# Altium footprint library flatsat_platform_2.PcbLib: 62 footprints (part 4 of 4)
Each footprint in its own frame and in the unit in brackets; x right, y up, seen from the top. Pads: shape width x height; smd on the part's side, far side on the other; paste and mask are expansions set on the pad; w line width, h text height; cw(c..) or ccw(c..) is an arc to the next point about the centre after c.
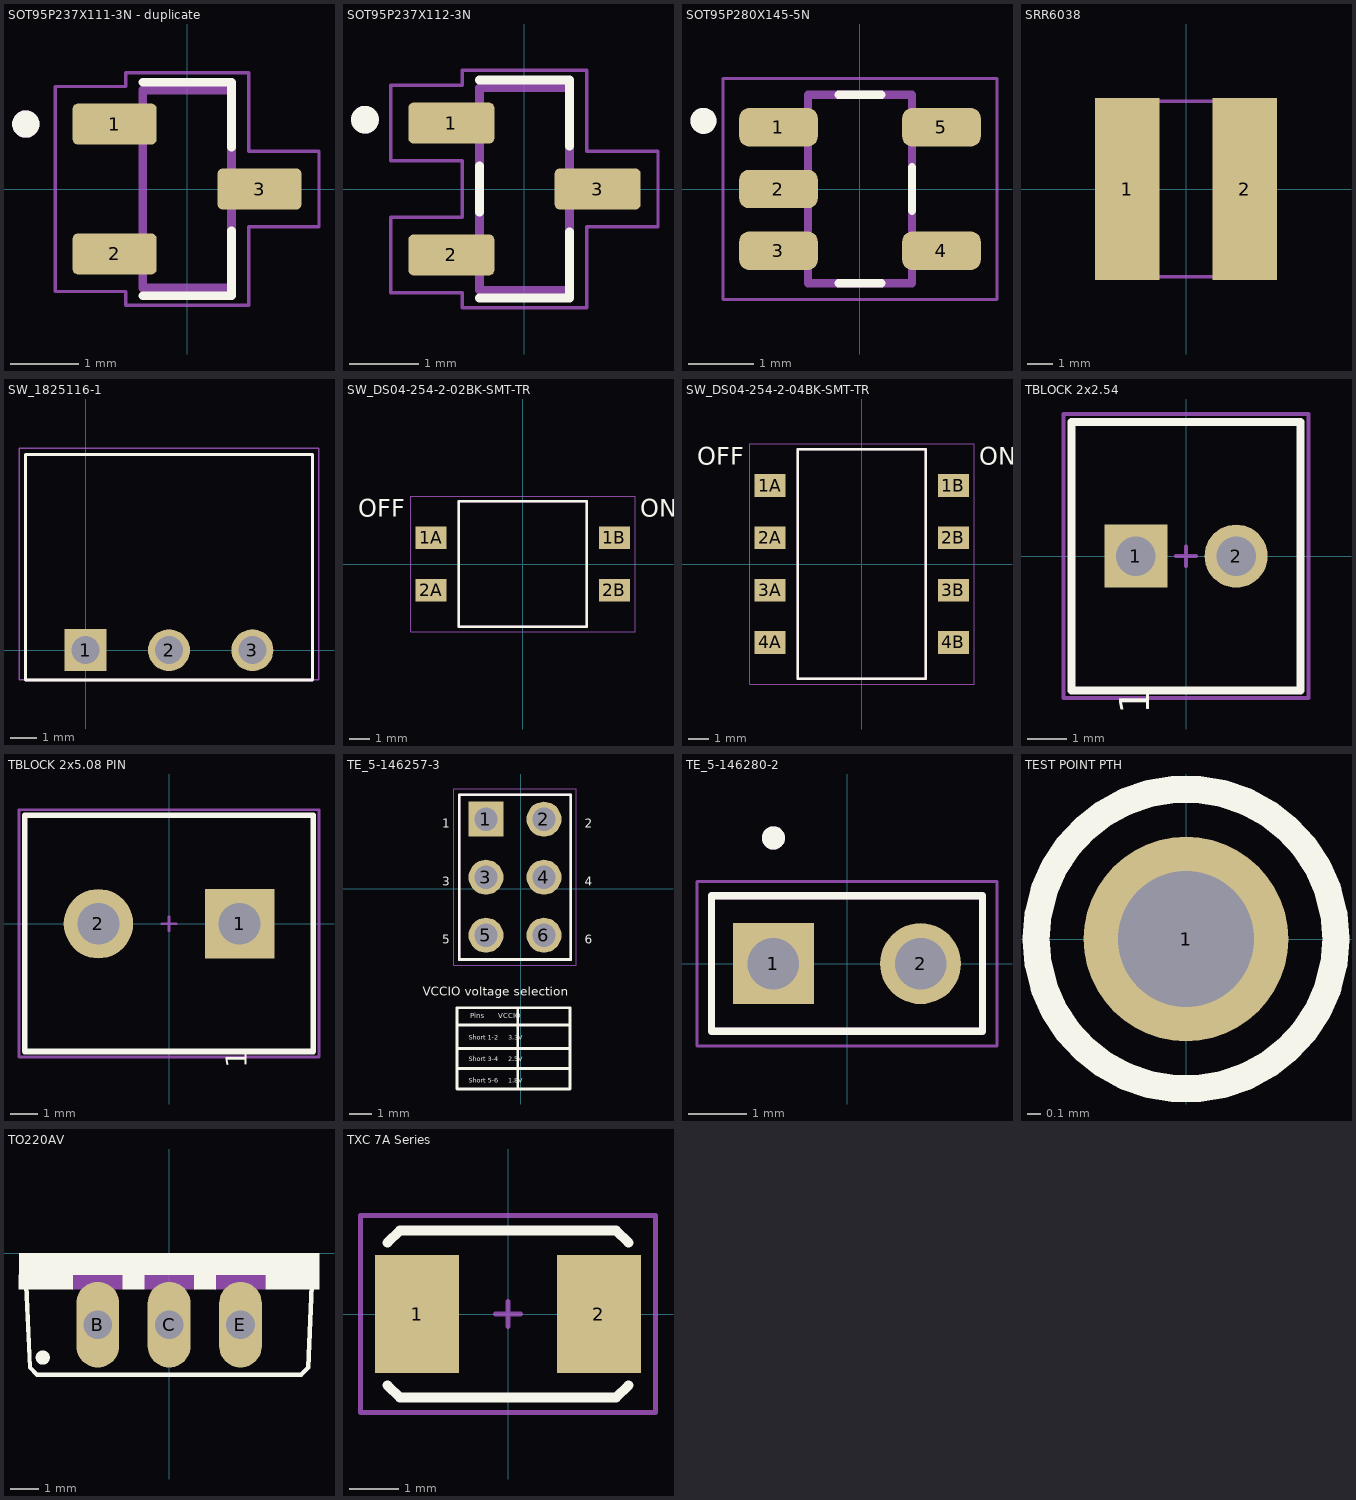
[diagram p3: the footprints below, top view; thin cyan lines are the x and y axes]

## SOT95P237X111-3N - duplicate [mm]
pads (3):
  rrect25% 1.23x0.6 smd: 1(-1.06,0.95) 2(-1.06,-0.95) 3(1.06,0)
Top Overlay:
  circle w0.2: c-2.36,0.95 r0.1
  lines w0.127: -0.65,-1.564 0.65,-1.564 0.65,-0.614 ; -0.65,1.564 0.65,1.564 0.65,0.614
Mechanical 13:
  circle w0.2: c-2.36,0.95 r0.1
  lines w0.127: -0.65,-1.45 -0.65,1.45 0.65,1.45 0.65,-1.45 -0.65,-1.45
Mechanical 15:
  lines w0.05: -1.93,-1.5 -0.9,-1.5 -0.9,-1.7 0.9,-1.7 0.9,-0.55 1.93,-0.55 1.93,0.55 0.9,0.55 0.9,1.7 -0.9,1.7 -0.9,1.5 -1.93,1.5 -1.93,-1.5
3D body "step_temp.STEP": height 1.11, standoff 0, extent -1.2,-1.45 1.2,1.45

## SOT95P237X112-3N [mm]
pads (3):
  rrect25% 1.24x0.59 smd: 1(-1.055,0.95) 2(-1.055,-0.95) 3(1.055,0)
Top Overlay:
  circle w0.2: c-2.3,1 r0.1
  lines w0.127: -0.65,-1.57 0.65,-1.57 0.65,-0.615 ; -0.65,-0.33 -0.65,0.33 ; -0.65,1.57 0.65,1.57 0.65,0.615
Mechanical 13:
  circle w0.2: c-2.3,1 r0.1
  lines w0.127: -0.65,-1.46 -0.65,1.46 0.65,1.46 0.65,-1.46 -0.65,-1.46
Mechanical 15:
  lines w0.05: -1.925,-1.495 -0.9,-1.495 -0.9,-1.71 0.9,-1.71 0.9,-0.545 1.925,-0.545 1.925,0.545 0.9,0.545 0.9,1.71 -0.9,1.71 -0.9,1.495 -1.925,1.495 -1.925,0.405 -0.9,0.405 -0.9,-0.405 -1.925,-0.405 -1.925,-1.495
3D body "TL431AIDBZT.STEP": height 1.12, standoff 0, extent -1.185,-1.46 1.185,1.46

## SOT95P280X145-5N [mm]
pads (5):
  rrect50% 1.21x0.59 smd: 1(-1.255,0.95) 2(-1.255,0) 3(-1.255,-0.95) 4(1.255,-0.95) 5(1.255,0.95)
Top Overlay:
  circle w0.2: c-2.41,1.05 r0.1
  lines w0.127: -0.33,-1.45 0.33,-1.45 ; -0.33,1.45 0.33,1.45 ; 0.8,-0.335 0.8,0.335
Mechanical 13:
  circle w0.2: c-2.41,1.05 r0.1
  lines w0.127: -0.8,-1.45 0.8,-1.45 0.8,1.45 -0.8,1.45 -0.8,-1.45
Mechanical 15:
  lines w0.05: -2.11,-1.7 -2.11,1.7 2.11,1.7 2.11,-1.7 -2.11,-1.7
3D body "NOPB.STEP": height 1.45, standoff 0, extent -1.4,-1.45 1.4,1.45

## SRR6038 [mil]
pads (2):
  rect 102x287 smd: 1(-92.5,0) 2(92.5,0)
Mechanical 13:
  lines w6: -138,-138 -138,138 138,138 138,-138 -138,-138
3D body "IND_BOURNS_SRR6038.step": height 158.11, standoff -0.12, extent -137.99,-138.1 138,138.12

## SW_1825116-1 [mm]
pads (3):
  rect 1.605x1.605 hole 1.07: 1(0,0)
  round 1.605 hole 1.07: 2(3.2,0) 3(6.4,0)
Top Overlay:
  lines w0.127: -2.3,-1.143 -2.3,7.5 8.7,7.5 8.7,-1.143 -2.3,-1.143
Mechanical 13:
  lines w0.127: -2.3,-1.143 -2.3,7.5 8.699,7.5 8.699,-1.143 -2.3,-1.143
Mechanical 15:
  lines w0.05: -2.55,-1.143 -2.55,7.75 8.95,7.75 8.95,-1.143 -2.55,-1.143
3D body "1825116-1.stp": height 5.61, standoff -4.15, extent -2.325,-0.261 8.675,12.239

## SW_DS04-254-2-02BK-SMT-TR [mm]
pads (4):
  rect 1.5x1.1 smd: 1A(-4.45,1.27) 1B(4.45,1.27) 2A(-4.45,-1.27) 2B(4.45,-1.27)
Top Overlay:
  lines w0.127: -3.1,-3.04 3.1,-3.04 3.1,3.04 -3.1,3.04 -3.1,-3.04
  text "OFF" at -8.001,2.286 h0.85
  text "ON" at 5.715,2.286 h0.85
Mechanical 13:
  lines w0.127: -3.1,-3.04 3.1,-3.04 3.1,3.04 -3.1,3.04 -3.1,-3.04
Mechanical 15:
  lines w0.05: -5.45,-3.29 -5.45,3.29 5.45,3.29 5.45,-3.29 -5.45,-3.29
3D body "CUI_DEVICES_DS04-254-2-02BK-SMT-TR.step": height 4.01, standoff 0.01, extent -4.95,-3.048 4.95,3.032

## SW_DS04-254-2-04BK-SMT-TR [mm]
pads (8):
  rect 1.5x1.1 smd: 1A(-4.45,3.81) 1B(4.45,3.81) 2A(-4.45,1.27) 2B(4.45,1.27) 3A(-4.45,-1.27) 3B(4.45,-1.27) 4A(-4.45,-3.81) 4B(4.45,-3.81)
Top Overlay:
  lines w0.127: -3.1,-5.58 3.1,-5.58 3.1,5.58 -3.1,5.58 -3.1,-5.58
  text "ON" at 5.715,4.826 h0.85
  text "OFF" at -8.001,4.826 h0.85
Mechanical 13:
  lines w0.127: -3.1,-5.58 3.1,-5.58 3.1,5.58 -3.1,5.58 -3.1,-5.58
Mechanical 15:
  lines w0.05: -5.45,-5.83 -5.45,5.83 5.45,5.83 5.45,-5.83 -5.45,-5.83
3D body "CUI_DEVICES_DS04-254-2-04BK-SMT-TR.step": height 4.01, standoff 0.01, extent -4.95,-5.572 4.95,5.588

## TBLOCK 2x2.54 [mm]
pads (2):
  rect 1.6x1.6 hole 1: 1(-1.27,0)
  round 1.6 hole 1: 2(1.27,0)
Top Overlay:
  lines w0.2: -2.9,-3.4 2.9,-3.4 2.9,3.4 -2.9,3.4 -2.9,-3.4
  text "1" at -0.93,-4 h0.76
Mechanical 15:
  lines w0.1: -0.25,0 0.25,0 ; 0,-0.25 0,0.25 ; -3.1,-3.6 -3.1,3.6 3.1,3.6 3.1,-3.6 -3.1,-3.6
3D body "c-282834-2-c-3d.STEP": height 10.1, standoff -3.3, extent -2.77,-3.25 2.77,3.25

## TBLOCK 2x5.08 PIN [mm]
pads (2):
  rect 2.5x2.5 hole 1.5: 1(2.54,0)
  round 2.5 hole 1.5: 2(-2.54,0)
Top Overlay:
  lines w0.2: -5.2,-4.6 -3.3,-4.6 5.2,-4.6 5.2,3.9 -5.2,3.9 -5.2,-4.6
  text "1" at 2.8,-5.2 h0.76
Mechanical 15:
  lines w0.1: -0.25,0 0.25,0 ; 0,-0.25 0,0.25 ; -5.4,-4.8 -5.4,4.1 5.4,4.1 5.4,-4.8 -5.4,-4.8
3D body "User Library-Terminal Block 2x5_08mm.step": height 12.1, standoff -4.5, extent -5.08,-4.45 5.08,3.75

## TE_5-146257-3 [mm]
pads (6):
  rect 1.53x1.53 hole 1.02: 1(-1.524,3.048)
  round 1.53 hole 1.02: 2(1.016,3.048) 3(-1.524,0.508) 4(1.016,0.508) 5(-1.524,-2.032) 6(1.016,-2.032)
Top Overlay:
  lines w0.127: -2.794,-7.874 2.159,-7.874 ; -2.794,-6.985 2.159,-6.985 ; -2.794,-5.969 2.159,-5.969 ; -2.794,-5.21 -2.794,-8.763 -1.778,-8.763 2.159,-8.763 ; -2.794,-5.207 2.159,-5.207 2.159,-8.758 ; -0.133,-8.761 -0.133,-5.21 ; -2.694,-3.102 -2.694,4.118 2.186,4.118 2.186,-3.102 -2.694,-3.102
  text "6" at 2.794,-2.413 h0.38
  text "5" at -3.429,-2.413 h0.38
  text "4" at 2.794,0.127 h0.38
  text "3" at -3.429,0.127 h0.38
  text "2" at 2.794,2.667 h0.38
  text "1" at -3.429,2.667 h0.38
  text "Pins       VCCIO" at -2.202,-5.659 h0.23
  text "VCCIO voltage selection" at -4.293,-4.674 h0.38
  text "Short 1-2     3.3V" at -2.286,-6.604 h0.2
  text "Short 3-4     2.5V" at -2.283,-7.557 h0.2
  text "Short 5-6     1.8V" at -2.283,-8.491 h0.2
Mechanical 13:
  lines w0.127: -2.694,-3.102 -2.694,4.118 2.186,4.118 2.186,-3.102 -2.694,-3.102
Mechanical 15:
  lines w0.05: -2.944,-3.352 -2.944,4.368 2.436,4.368 2.436,-3.352 -2.944,-3.352
3D body "5-146257-3--3DModel-STEP-1.STEP": height 8.14, standoff -3.04, extent -2.692,-3.099 2.184,4.115

## TE_5-146280-2 [mm]
pads (2):
  rect 1.398x1.398 hole 0.89: 1(-1.27,0)
  round 1.398 hole 0.89: 2(1.27,0)
Top Overlay:
  circle w0.2: c-1.27,2.17 r0.1
  lines w0.127: -2.34,-1.17 2.34,-1.17 2.34,1.17 -2.34,1.17 -2.34,-1.17
Mechanical 13:
  circle w0.2: c-1.27,2.17 r0.1
  lines w0.127: -2.34,-1.17 2.34,-1.17 2.34,1.17 -2.34,1.17 -2.34,-1.17
Mechanical 15:
  lines w0.05: -2.59,-1.42 2.59,-1.42 2.59,1.42 -2.59,1.42 -2.59,-1.42
3D body "5-146280-2--3DModel-STEP-1.STEP": height 8.14, standoff -3.04, extent -2.337,-1.168 2.337,1.168

## TEST POINT PTH [mm]
pads (1):
  round 1.5 hole 1: 1(0,0)
Top Overlay:
  circle w0.2: c0,0 r1.1

## TO220AV [mil]
pads (3):
  oval 60x120 hole 40: B(-100,-100) C(0,-100) E(100,-100)
Top Overlay:
  circle w10: c-177,-146 r5
  region: 210,-30.05 -210.35,-30.05 -210.35,0 210,0
  region: -135,-50.02 -210.35,-50.02 -210.35,-30 -135,-30
  region: -35,-50.06 -65.08,-50.06 -65.08,-30 -35,-30
  region: 65,-50.06 35.04,-50.06 35.04,-30 65,-30
  region: 210,-50.02 135.05,-50.02 135.05,-30 210,-30
  lines w6: -200,-45 -195,-160 -185,-170 185,-170 195,-160 200,-45
Mechanical 13:
  region: -65,-50.01 -135.01,-50.01 -135.01,-30 -65,-30
  region: 35,-50.03 -35.02,-50.03 -35.02,-30 35,-30
  region: 135,-50.06 65.08,-50.06 65.08,-30 135,-30
3D body "TIP41C.STEP": height 617.19, standoff -531.41, extent -200.79,-215 200.79,56.34

## TXC 7A Series [mm]
height 0.9
pads (2):
  rect 1.7x2.4 smd: 1(-1.85,0) 2(1.85,0)
Top Overlay:
  lines w0.2: -2.45,-1.45 -2.2,-1.7 2.2,-1.7 2.45,-1.45 ; -2.45,1.45 -2.2,1.7 2.2,1.7 2.45,1.45
Top Assembly:
  lines w0.1: -0.25,0 0.25,0 ; 0,-0.25 0,0.25 ; -3,-2 3,-2 3,2 -3,2 -3,-2
  text "'.Designator'" at -2.5,0.75 h0.8
3D body "User Library-445-CRYTAL-SMD.STEP": height 1.35, standoff 0, extent -2.5,-1.6 2.5,1.6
